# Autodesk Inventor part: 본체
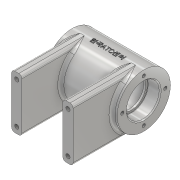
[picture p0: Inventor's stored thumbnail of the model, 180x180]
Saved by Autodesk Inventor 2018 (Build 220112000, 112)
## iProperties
Created: 2020-07
Part Number: 본체
Material: 알루미늄 6061-AHC
Document SubType Name: Modeling
Designer: Administrator
Density: 2.7 g/cm^3
Appearance: 알루미늄 - 짙음
Mass: 305.294 g
Surface Area: 357.55 cm^2
Volume: 113.072 cm^3
Author: Administrator
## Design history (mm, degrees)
sketch "스케치1"
  geometry: L1 (35, 26)-(-35, 26); L2 (-35, 26)-(-35, 16); L3 (-35, 0)-(35, 0); L4 (35, 26)-(35, 16); L5 (35, 16)-(23, 16); L6 (23, 16)-(23, 14); L7 (23, 14)-(21, 14); L8 (21, 14)-(21, 21); L9 (21, 21)-(-21, 21); L10 (-21, 21)-(-21, 14); L11 (-21, 14)-(-23, 14); L12 (-23, 14)-(-23, 16); L13 (-23, 16)-(-35, 16); 1 further point
  constraints: 26 end point, 5 perpendicular, 4 horizontal, 2 parallel, 2 vertical
  dimensions: "d1" = 26 distance of L3.end L1.start; "d2" = 70 distance of L1.start L1.end; "d3" = 16 distance of L3.end L4.end; "d7" = 2 distance of L7.end L6.end; "d9" = 42 distance of L8.end L9.end; "d10" = 7 distance of L9.end L10.end; "d11" = 2 distance of L10.end L11.end; "d12" = 2 distance of L11.end L12.end; "d13" = 7 distance of L7.end L8.end; "d14" = 12 distance between parallel lines of L6 L4; "d15" = 2 distance between parallel lines of L5 L7; "d16" = 10 distance between parallel lines of L5 L1; "d17" = 35 distance from line of point (0, 0) L4; "d18" = 16 distance from line of point (0, 0) L5; "d19" = 70 distance from line of L3.start L4
revolve "회전1" sketch "스케치1" stored, may be unused: angle "d20" = 90 deg
chamfer "모따기1" distance "d21" = 1; stored, may be unused: second distance "d22" = 2, angle "d23" = 45 deg
fillet "모깎기1" dims "d24" = 3
fillet "모깎기2" dims "d25" = 0.3
sketch "스케치2"
  geometry: A1 r 21 centre (0, 0) between (0, 21) and (0, -21); A2 r 21 centre (0, 0) between (0, 21) and (-21, 0) reference; 2 further points
  constraints: 4 point on circle, 1 centre point, 1 coincident
  dimensions: "d26" = 42 diameter of A1
hole "구멍1" sketch "스케치2" at (0, 21), (-21, 0), (0, -21), (21, 0) diameter "d27" = 3.242; stored, may be unused: countersink angle "d31" = 90 deg, drill point angle "d33" = 118 deg; dims "d28" = 8, "d29" = 4, "d30" = 2, "d32" = 10
node "작업 평면1"
sketch "스케치3"
  geometry: C1 r 5 at (0, 0); 1 further point
  constraints: 1 centre point, 1 coincident
  dimensions: "d35" = 10 diameter of C1
extrude "돌출1" join sketch "스케치3" stored distance "d36" = 10; taper "d37" = 0 deg
sketch "스케치4"
  geometry: 2 further points
  constraints: 1 coincident
hole "구멍2" sketch "스케치4" at (0, 0) diameter "d38" = 4.917; stored, may be unused: countersink angle "d42" = 90 deg, drill point angle "d44" = 118 deg; dims "d39" = 20, "d40" = 4, "d41" = 2, "d43" = 20
fillet "모깎기4" dims "d60" = 2
node "작업 평면2"
sketch "스케치7"
  geometry: L1 (0, 0)-(30, 0); L2 (30, 0)-(30, 26); L3 (30, 0)-(30, -26); L4 (30, -26)-(20, -26); L5 (35, -26)-(-35, -26) reference; L6 (20, -26)-(20, 26); L7 (20, 26)-(30, 26)
  constraints: 12 end point, 3 vertical, 1 horizontal, 1 point on line
  dimensions: "d62" = 30 distance of L1.start L1.end; "d63" = 26 distance of L1.end L2.end; "d66" = 26 distance of L1.end L3.end; "d67" = 10 distance of L3.end L4.end; "d69" = 52 distance of L4.end L6.end
extrude "돌출2" join sketch "스케치7" stored distance "d70" = 26 (= d66); taper "d71" = 0 deg
fillet "모깎기5" dims "d72" = 3
fillet "모깎기6" dims "d73" = 3
sketch "스케치8"
  geometry: L1 (0, 0)-(0, 20); L2 (0, 20)-(-64.656, 20); L3 (-27, 26)-(-23, 26) reference; L4 (-25, 26)-(-25, 11.9); L5 (-25, 22.621)-(-25, 19.379) reference; 2 further points
  constraints: 6 end point, 2 point on line, 2 vertical, 1 midpoint
  dimensions: "d74" = 20 distance of L1.start L1.end
hole "구멍4" sketch "스케치8" at (-25, 20) diameter "d75" = 4.134; stored, may be unused: countersink angle "d79" = 90 deg, drill point angle "d81" = 118 deg; dims "d76" = 8, "d77" = 4, "d78" = 2, "d80" = 10
sketch "스케치10"
  geometry: L1 (0, 0)-(-27.251, -9.919); L2 (-27.251, -9.919)-(-25.199, -15.557); L3 (-25.199, -15.557)-(-19.222, -13.381); L4 (-19.222, -13.381)-(-21.274, -7.743); L5 (-21.274, -7.743)-(-27.251, -9.919); A1 r 29 centre (0, 0) between (-17.664, 23) and (-17.664, -23) reference
  constraints: 10 end point, 1 perpendicular, 1 point on line, 1 tangent
  dimensions: "d87" = 29 distance of L1.start L1.end; "d89" = 12 diameter of L2.end L1
revolve "회전3" sketch "스케치10" stored, may be unused: angle "d90" = 90 deg
sketch "스케치11"
  geometry: 2 further points
  constraints: 1 coincident
hole "구멍5" sketch "스케치11" at (0, 0) diameter "d91" = 5.188; stored, may be unused: countersink angle "d95" = 90 deg, drill point angle "d97" = 118 deg; dims "d92" = 20, "d93" = 4, "d94" = 2, "d96" = 16
fillet "모깎기7" dims "d98" = 2
node "작업 평면4"
sketch "스케치12"
  geometry: L1 (-35, -26)-(-35, 26) reference; L2 (-35, 26)-(35, 26) reference; 2 further points
  constraints: 1 other
  dimensions: "d99" = 35 distance from line of L1 point (0, 0); "d100" = 26 distance from line of L2 point (0, 0)
feature "엠보싱2" sketch "스케치12" dims "d101" = 0.5, "d102" = 0
node "솔리드1"
mirror "미러1"
mirror "미러2"
mirror "미러5"
mirror "미러6"
other parameters: "d34" = 29, "d61" = -64
